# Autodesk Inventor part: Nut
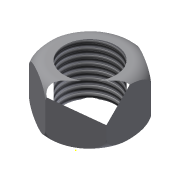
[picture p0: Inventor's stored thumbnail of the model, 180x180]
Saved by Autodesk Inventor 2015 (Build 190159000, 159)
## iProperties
Created: 2010-03
Part Number: Nut
Document SubType Name: Modeling
Designer: bhakira
Density: 1 g/cm^3
Material: Generic
Appearance: Default
Author: bhakira
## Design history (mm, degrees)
sketch "Sketch1"
  geometry: L1 (0, 17.321)-(15, 8.66); L2 (15, 8.66)-(15, -8.66); L3 (15, -8.66)-(0, -17.321); L4 (0, -17.321)-(-15, -8.66); L5 (-15, -8.66)-(-15, 8.66); L6 (-15, 8.66)-(0, 17.321); 2 further points
  constraints: 12 end point, 1 coincident, 13 other
  dimensions: "d0" = 30 distance between parallel lines of L2 L5
extrude "Extrusion1" new body sketch "Sketch1" distance "d1" = 20; taper "d2" = 0 deg
sketch "Sketch2"
  geometry: L1 (0, 17.321)-(-15, 8.66) reference; L2 (-15, 8.66)-(-15, -8.66) reference; L3 (-15, -8.66)-(0, -17.321) reference; L4 (0, -17.321)-(15, -8.66) reference; L5 (15, -8.66)-(15, 8.66) reference; L6 (15, 8.66)-(0, 17.321) reference
sketch "Sketch3"
  geometry: C1 r 10 at (0, 0); 1 further point
  constraints: 1 centre point, 1 coincident
  dimensions: "d4" = 20 diameter of C1
extrude "Extrusion2" cut sketch "Sketch3" stored distance "d5" = 15; taper "d6" = 0 deg
thread "Thread1" dims "d7" = 10, "d8" = 0
sketch "Sketch5"
  geometry: L1 (-17.321, 20)-(-8.66, 20) reference; L2 (-17.321, 20)-(-8.66, 20) reference; L3 (-8.66, 0)-(-8.66, 20) reference; L4 (-17.321, 0)-(-8.66, 0) reference; L5 (-17.321, 0)-(-17.321, 20) reference; L6 (0, -8)-(0, 24); L7 (-12.035, 20)-(-17.321, 20); A1 r 5.286 centre (-12.035, 14.714) between (-12.035, 20) and (-17.321, 14.714); 1 further point
  constraints: 4 end point, 3 tangent, 2 point on circle, 2 point on line, 1 centre point, 1 collinear, 1 parallel
revolve "Revolution1" sketch "Sketch5" stored, may be unused: angle "d16" = 90 deg
sketch "Sketch6"
  geometry: 1 further point
workplane "Work Plane1"
mirror "Mirror1"
body "Solid1"
node "Projected Loop1"
